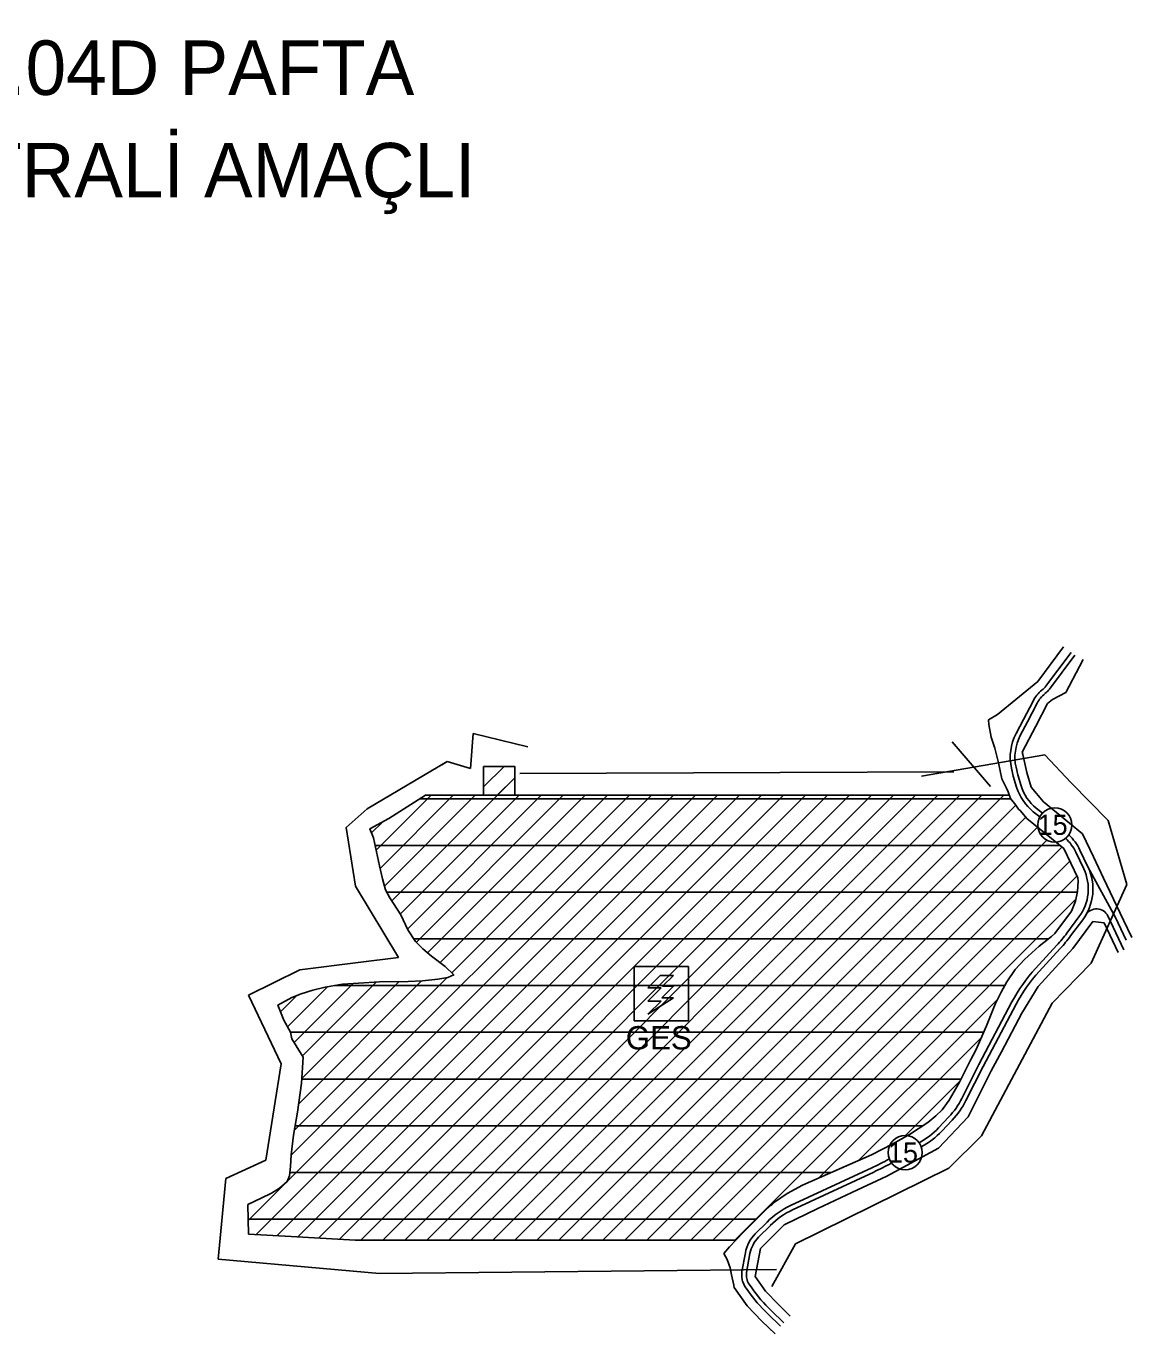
# Model space of a CAD drawing. Extents: x 449035 to 450868, y 4452351 to 4453762.
# Drawn here: x 450158 to 450868, y 4452922 to 4453762 of the extents above; entities that cross this region are included whole.
import ezdxf

# ---------------------------------------------------------------- set-up
doc = ezdxf.new("R2010")
doc.units = 0
for name, color, linetype in [('ADAKENARI', 7, 'Continuous'), ('KALDIRIM', 7, 'Continuous'), ('KD_DAIRE', 7, 'Continuous'), ('KD_YGEN', 7, 'Continuous'), ('LEJAND', 7, 'Continuous'), ('PL_ENERJI_URETIM_ALANI', 7, 'Continuous'), ('SN_ONAY', 7, 'Continuous'), ('TR_ENERJİSANTRALİ', 7, 'Continuous')]:
    doc.layers.add(name, color=color, linetype=linetype)

msp = doc.modelspace()

# ---------------------------------------------------------------- linework, layer by layer
at = {"layer": 'ADAKENARI'}
for p, q in [((450824.18, 4453363.2), (450807.57, 4453340.96)), ((450825.74, 4453333.78), (450834.53, 4453350.62)), ((450834.53, 4453350.62), (450836.81, 4453354.98)), ((450807.57, 4453340.96), (450781.78, 4453319.66)), ((450817.01, 4453329.31), (450825.74, 4453333.78)), ((450806.35, 4453312.31), (450813.88, 4453326.71)), ((450813.88, 4453326.71), (450817.01, 4453329.31)), ((450781.78, 4453319.66), (450776.04, 4453316.41)), ((450776.04, 4453316.41), (450776.14, 4453313.23)), ((450776.14, 4453313.23), (450777.78, 4453305.26)), ((450797.56, 4453295.47), (450806.35, 4453312.31)), ((450777.78, 4453305.26), (450780.06, 4453298.05)), ((450780.06, 4453298.05), (450782.35, 4453288.76)), ((450797.98, 4453294.12), (450797.56, 4453295.47)), ((450800.55, 4453282.48), (450797.98, 4453294.12)), ((450451.63, 4453286.37), (450471.63, 4453286.38)), ((450451.63, 4453267.87), (450451.63, 4453286.37)), ((450471.63, 4453286.38), (450471.63, 4453267.88)), ((450782.35, 4453288.76), (450784.61, 4453278.47)), ((450803.49, 4453273), (450800.55, 4453282.48)), ((450784.61, 4453278.47), (450787.46, 4453272.39)), ((450390.67, 4453252.84), (450414.21, 4453267.86)), ((450390.67, 4453252.84), (450414.21, 4453267.86)), ((450390.67, 4453252.84), (450414.21, 4453267.86)), ((450390.67, 4453252.84), (450414.21, 4453267.86)), ((450414.21, 4453267.86), (450789.35, 4453267.95)), ((450414.21, 4453267.86), (450604.66, 4453267.86)), ((450604.66, 4453267.86), (450760.62, 4453267.94)), ((450787.46, 4453272.39), (450788.71, 4453270)), ((450788.71, 4453270), (450790.03, 4453265.75)), ((450790.03, 4453265.75), (450793.57, 4453261.44)), ((450811.24, 4453263.57), (450803.49, 4453273)), ((450793.57, 4453261.44), (450795.26, 4453258.99)), ((450795.26, 4453258.99), (450796.46, 4453257.93)), ((450796.46, 4453257.93), (450800.61, 4453252.88)), ((450836.35, 4453243.16), (450811.24, 4453263.57)), ((450378.54, 4453246.21), (450390.67, 4453252.84)), ((450800.61, 4453252.88), (450824.27, 4453233.65)), ((450380.9, 4453240.56), (450378.54, 4453246.21)), ((450384.82, 4453222.49), (450380.9, 4453240.56)), ((450843.48, 4453228.19), (450836.35, 4453243.16)), ((450824.27, 4453233.65), (450833.29, 4453214.69)), ((450849.92, 4453214.64), (450843.48, 4453228.19)), ((450386.62, 4453214.14), (450384.82, 4453222.49)), ((450388.63, 4453207.09), (450386.62, 4453214.14)), ((450391.4, 4453201.98), (450388.63, 4453207.09)), ((450833.53, 4453212.67), (450833.25, 4453206.06)), ((450833.29, 4453214.69), (450833.53, 4453212.67)), ((450856.36, 4453201.09), (450849.92, 4453214.64)), ((450398.38, 4453190.97), (450391.4, 4453201.98)), ((450831.92, 4453199.81), (450829.4, 4453193.37)), ((450833.25, 4453206.06), (450831.92, 4453199.81)), ((450862.81, 4453187.55), (450856.36, 4453201.09)), ((450402.95, 4453181.4), (450398.38, 4453190.97)), ((450829.4, 4453193.37), (450818.7, 4453179.06)), ((450407.91, 4453173.99), (450402.95, 4453181.4)), ((450830.26, 4453169.47), (450843.1, 4453186.64)), ((450843.09, 4453186.64), (450850.3, 4453185.92)), ((450850.3, 4453185.92), (450859.36, 4453166.85)), ((450868.07, 4453176.5), (450862.81, 4453187.55)), ((450412.59, 4453169.17), (450407.91, 4453173.99)), ((450816.52, 4453177.06), (450808.48, 4453170.81)), ((450818.66, 4453179.01), (450816.52, 4453177.06)), ((450818.7, 4453179.06), (450818.66, 4453179.01)), ((450418.16, 4453164.49), (450412.59, 4453169.17)), ((450808.48, 4453170.81), (450799.04, 4453162.33)), ((450807.85, 4453145.06), (450830.26, 4453169.47)), ((450426.94, 4453157.87), (450418.16, 4453164.49)), ((450432.47, 4453152.47), (450426.94, 4453157.87)), ((450799.04, 4453162.33), (450793.2, 4453155.91)), ((450371.23, 4453147.14), (450384.82, 4453148.08)), ((450371.23, 4453147.14), (450384.82, 4453148.08)), ((450384.82, 4453148.08), (450403.2, 4453148.22)), ((450384.82, 4453148.08), (450403.2, 4453148.22)), ((450403.2, 4453148.22), (450412.33, 4453148.58)), ((450403.2, 4453148.22), (450412.33, 4453148.58)), ((450412.33, 4453148.58), (450422.19, 4453149.59)), ((450412.33, 4453148.58), (450422.19, 4453149.59)), ((450422.19, 4453149.59), (450428.59, 4453150.74)), ((450422.19, 4453149.59), (450428.59, 4453150.74)), ((450428.59, 4453150.74), (450432.47, 4453152.47)), ((450428.59, 4453150.74), (450432.47, 4453152.47)), ((450787.83, 4453148), (450784.07, 4453141.3)), ((450793.2, 4453155.91), (450787.83, 4453148)), ((450328.4, 4453137.86), (450334.51, 4453140.31)), ((450328.4, 4453137.86), (450334.51, 4453140.31)), ((450334.51, 4453140.31), (450341.92, 4453142.61)), ((450334.51, 4453140.31), (450341.92, 4453142.61)), ((450341.92, 4453142.61), (450349.9, 4453144.48)), ((450341.92, 4453142.61), (450349.9, 4453144.48)), ((450349.9, 4453144.48), (450360.94, 4453146.42)), ((450349.9, 4453144.48), (450360.94, 4453146.42)), ((450360.94, 4453146.42), (450371.23, 4453147.14)), ((450360.94, 4453146.42), (450371.23, 4453147.14)), ((450784.07, 4453141.3), (450780.29, 4453133.73)), ((450797.36, 4453127.77), (450807.85, 4453145.06)), ((450319.53, 4453133.01), (450328.4, 4453137.86)), ((450319.53, 4453133.01), (450328.4, 4453137.86)), ((450323.28, 4453123.26), (450319.53, 4453133.01)), ((450323.28, 4453123.26), (450319.53, 4453133.01)), ((450780.29, 4453133.73), (450774.78, 4453119.79)), ((450327.58, 4453115.55), (450323.28, 4453123.26)), ((450327.58, 4453115.55), (450323.28, 4453123.26)), ((450784.24, 4453102.96), (450797.36, 4453127.77)), ((450328.36, 4453111.35), (450327.58, 4453115.55)), ((450328.36, 4453111.35), (450327.58, 4453115.55)), ((450774.78, 4453119.79), (450767.83, 4453104)), ((450335.77, 4453099.64), (450328.36, 4453111.35)), ((450335.77, 4453099.64), (450328.36, 4453111.35)), ((450334.55, 4453082.96), (450335.77, 4453099.64)), ((450334.55, 4453082.96), (450335.77, 4453099.64)), ((450764.46, 4453097.64), (450757.1, 4453082.99)), ((450767.83, 4453104), (450764.46, 4453097.64)), ((450777.8, 4453090.76), (450784.24, 4453102.96)), ((450763, 4453061.34), (450777.8, 4453090.76)), ((450332.01, 4453064.32), (450334.55, 4453082.96)), ((450332.01, 4453064.32), (450334.55, 4453082.96)), ((450757.1, 4453082.99), (450755.63, 4453080.5)), ((450755.63, 4453080.5), (450750.72, 4453072.02)), ((450329.4, 4453049.39), (450332.01, 4453064.32)), ((450329.4, 4453049.39), (450332.01, 4453064.32)), ((450746.25, 4453065.69), (450742.19, 4453061.96)), ((450750.72, 4453072.02), (450746.25, 4453065.69)), ((450736.96, 4453057.64), (450725.21, 4453049.89)), ((450742.19, 4453061.96), (450736.96, 4453057.64)), ((450743.95, 4453041.17), (450763, 4453061.34)), ((450328.11, 4453036.82), (450329.4, 4453049.39)), ((450328.11, 4453036.82), (450329.4, 4453049.39)), ((450725.21, 4453049.89), (450714.62, 4453043.87)), ((450714.62, 4453043.87), (450700.84, 4453036.86)), ((450710.63, 4453023.07), (450743.95, 4453041.17)), ((450327.67, 4453029.33), (450328.11, 4453036.82)), ((450327.67, 4453029.33), (450328.11, 4453036.82)), ((450700.84, 4453036.86), (450683.69, 4453029.43)), ((450325.37, 4453019.76), (450326.95, 4453023.43)), ((450325.37, 4453019.76), (450326.95, 4453023.43)), ((450326.95, 4453023.43), (450327.67, 4453029.33)), ((450326.95, 4453023.43), (450327.67, 4453029.33)), ((450667.14, 4453022.13), (450656.55, 4453017.25)), ((450683.69, 4453029.43), (450667.14, 4453022.13)), ((450691.77, 4453014.29), (450710.63, 4453023.07)), ((450315.41, 4453012.13), (450320.59, 4453015.52)), ((450315.41, 4453012.13), (450320.59, 4453015.52)), ((450320.59, 4453015.52), (450325.37, 4453019.76)), ((450320.59, 4453015.52), (450325.37, 4453019.76)), ((450656.55, 4453017.25), (450646.67, 4453012.04)), ((450666.34, 4453002.45), (450691.77, 4453014.29)), ((450300.2, 4453004.86), (450308.79, 4453009.04)), ((450300.2, 4453004.86), (450308.79, 4453009.04)), ((450308.79, 4453009.04), (450315.41, 4453012.13)), ((450308.79, 4453009.04), (450315.41, 4453012.13)), ((450638.48, 4453006.34), (450636.69, 4453004.72)), ((450646.67, 4453012.04), (450638.48, 4453006.34)), ((450300.63, 4452985.94), (450300.2, 4453004.86)), ((450300.63, 4452985.94), (450300.2, 4453004.86)), ((450631.5, 4453000.03), (450618.62, 4452987.09)), ((450632.58, 4453001.01), (450631.5, 4453000.03)), ((450635.92, 4453004.35), (450632.58, 4453001.01)), ((450636.69, 4453004.72), (450635.92, 4453004.35)), ((450644.75, 4452991.96), (450666.34, 4453002.45)), ((450629.44, 4452976.65), (450644.75, 4452991.96)), ((450300.63, 4452985.94), (450328, 4452984.35)), ((450328, 4452984.35), (450300.63, 4452985.94)), ((450328, 4452984.35), (450369.18, 4452982.12)), ((450369.18, 4452982.12), (450328, 4452984.35)), ((450369.2, 4452982.12), (450454.69, 4452982.12)), ((450369.2, 4452982.12), (450454.69, 4452982.12)), ((450454.69, 4452982.12), (450613.75, 4452982.12)), ((450454.69, 4452982.12), (450613.75, 4452982.12)), ((450618.62, 4452987.09), (450609.5, 4452977.79)), ((450609.5, 4452977.79), (450605.94, 4452973.38)), ((450605.94, 4452973.38), (450608.03, 4452969.59)), ((450626.18, 4452958.58), (450629.44, 4452976.65)), ((450608.03, 4452969.59), (450610.09, 4452964.14)), ((450610.09, 4452964.14), (450610.88, 4452959.84)), ((450610.88, 4452959.84), (450612.46, 4452953.19)), ((450632.68, 4452949.27), (450626.18, 4452958.58)), ((450612.28, 4452952.87), (450612.46, 4452953.19)), ((450612.28, 4452952.87), (450612.68, 4452951.7)), ((450612.68, 4452951.7), (450621.05, 4452939.73)), ((450640.97, 4452940.63), (450632.68, 4452949.27)), ((450621.05, 4452939.73), (450630.34, 4452930.05)), ((450648.63, 4452933.21), (450640.97, 4452940.63)), ((450630.34, 4452930.05), (450638.83, 4452921.83))]:
    msp.add_line(p, q, dxfattribs=at)
at = {"layer": 'KALDIRIM'}
for p, q in [((450828.98, 4453359.61), (450812.68, 4453337.77)), ((450831.39, 4453357.81), (450815.08, 4453335.98)), ((450810.29, 4453335.43), (450811.06, 4453336.06)), ((450812.2, 4453333.12), (450812.97, 4453333.76)), ((450798.37, 4453316.48), (450804.6, 4453328.39)), ((450801.03, 4453315.09), (450807.26, 4453327)), ((450793.71, 4453307.55), (450798.37, 4453316.48)), ((450796.37, 4453306.16), (450801.03, 4453315.09)), ((450791.84, 4453280.17), (450790.74, 4453285.16)), ((450794.74, 4453280.94), (450793.67, 4453285.8)), ((450794.04, 4453273.09), (450791.84, 4453280.17)), ((450796.9, 4453273.97), (450794.74, 4453280.94)), ((450808.86, 4453253.9), (450804.75, 4453257.25)), ((450810.61, 4453256.35), (450806.64, 4453259.57)), ((450839.88, 4453221.78), (450834.73, 4453232.62)), ((450837.17, 4453220.49), (450832.02, 4453231.33)), ((450857.52, 4453189.35), (450839.88, 4453221.78)), ((450852.66, 4453190.28), (450862.97, 4453168.57)), ((450826.35, 4453179.27), (450834.11, 4453189.65)), ((450828.75, 4453177.47), (450836.51, 4453187.85)), ((450864.46, 4453174.78), (450857.52, 4453189.35)), ((450806.25, 4453156.63), (450819.91, 4453171.5)), ((450808.46, 4453154.6), (450822.12, 4453169.47)), ((450769.84, 4453094.96), (450791.06, 4453135.11)), ((450772.5, 4453093.59), (450793.71, 4453133.7)), ((450758.84, 4453073.1), (450769.84, 4453094.96)), ((450761.52, 4453071.75), (450772.5, 4453093.59)), ((450743.87, 4453054.19), (450750.52, 4453061.24)), ((450746.05, 4453052.13), (450752.7, 4453059.18)), ((450712.04, 4453034.08), (450712.24, 4453034.19)), ((450713.47, 4453031.44), (450713.72, 4453031.58)), ((450648.81, 4453004.22), (450700.99, 4453028.51)), ((450650.08, 4453001.5), (450702.26, 4453025.79)), ((450626.17, 4452986.12), (450633.71, 4452993.65)), ((450628.3, 4452983.99), (450635.83, 4452991.53)), ((450617.62, 4452961.82), (450619.8, 4452973.94)), ((450620.57, 4452961.28), (450622.75, 4452973.4)), ((450621.44, 4452949.65), (450619.75, 4452952.07)), ((450623.9, 4452951.37), (450622.21, 4452953.78)), ((450642.37, 4452926.75), (450634.23, 4452934.63)), ((450644.45, 4452928.9), (450636.31, 4452936.79))]:
    msp.add_line(p, q, dxfattribs=at)
for centre, radius, start, end in [((450824.98, 4453317.73), 23, 129.71534, 152.3941), ((450824.98, 4453317.73), 20, 129.71534, 152.3941), ((450804.67, 4453343.76), 10, 309.71534, 323.24646), ((450804.67, 4453343.76), 13, 309.71534, 323.24646), ((450822.96, 4453292.28), 33, 152.43664, 192.45887), ((450822.96, 4453292.28), 30, 152.43664, 192.45887), ((450825.56, 4453282.86), 30, 197.22103, 230.90214), ((450825.56, 4453282.86), 33, 197.22103, 230.90214), ((450804.93, 4453218.44), 30, 25.4361, 46.61051), ((450804.93, 4453218.44), 33, 25.4361, 46.6385), ((450810.08, 4453207.61), 30, 323.22249, 25.4361), ((450810.08, 4453207.61), 33, 323.22249, 25.4361), ((450845.43, 4453186.84), 8, 25.42651, 149.56601), ((450746.25, 4453239.14), 100, 317.43838, 323.22249), ((450746.25, 4453239.14), 103, 317.43838, 323.22249), ((450882.12, 4453086.96), 103, 137.43838, 152.13345), ((450882.12, 4453086.96), 100, 137.43838, 152.13345), ((450714.17, 4453095.57), 50, 316.63566, 333.29481), ((450714.17, 4453095.57), 53, 316.63566, 333.29481), ((450707.52, 4453088.52), 50, 298.51149, 316.63566), ((450707.52, 4453088.52), 53, 298.51149, 316.63566), ((450616.57, 4453209.82), 200, 294.9671, 298.51149), ((450616.57, 4453209.82), 203, 294.9671, 298.51149), ((450671.18, 4452956.17), 53, 114.9671, 134.99991), ((450671.18, 4452956.17), 50, 114.9671, 134.99991), ((450642.44, 4452969.85), 23, 134.99991, 169.77321), ((450642.44, 4452969.85), 20, 134.99991, 169.77321), ((450630.41, 4452959.51), 13, 169.77321, 214.92166), ((450630.41, 4452959.51), 10, 169.77321, 214.92166), ((450705.89, 4453008.61), 103, 214.92166, 225.91171), ((450705.89, 4453008.61), 100, 214.92166, 225.91171)]:
    msp.add_arc(centre, radius, start, end, dxfattribs=at)
at = {"layer": 'KD_DAIRE'}
for centre in [(450818.6, 4453248.78), (450722.46, 4453038.25)]:
    msp.add_circle(centre, 11, dxfattribs=at)
at = {"layer": 'LEJAND'}
for p, q in [((450548.35, 4453157.92), (450583.35, 4453157.92)), ((450548.35, 4453157.92), (450548.35, 4453122.92)), ((450583.35, 4453157.92), (450583.35, 4453122.92)), ((450565.14, 4453152.13), (450557.14, 4453144.13)), ((450573.63, 4453152.13), (450565.14, 4453152.13)), ((450566.63, 4453145.13), (450573.63, 4453152.13)), ((450557.14, 4453144.13), (450565.63, 4453144.13)), ((450565.63, 4453144.13), (450557.14, 4453135.65)), ((450566.14, 4453137.65), (450573.63, 4453145.13)), ((450573.63, 4453145.13), (450566.63, 4453145.13)), ((450557.14, 4453127.16), (450573.63, 4453137.65)), ((450557.14, 4453135.65), (450565.63, 4453135.65)), ((450565.63, 4453135.65), (450557.14, 4453127.16)), ((450573.63, 4453137.65), (450566.14, 4453137.65)), ((450548.35, 4453122.92), (450583.35, 4453122.92))]:
    msp.add_line(p, q, dxfattribs=at)
at = {"layer": 'PL_ENERJI_URETIM_ALANI'}
for points in [[(450451.63, 4453286.37), (450471.63, 4453286.38), (450471.63, 4453267.88), (450451.63, 4453267.87)], [(450414.21, 4453267.86), (450760.62, 4453267.94), (450789.35, 4453267.95), (450788.71, 4453270), (450788.71, 4453270), (450787.46, 4453272.39), (450788.71, 4453270), (450790.03, 4453265.75), (450793.57, 4453261.44), (450795.26, 4453258.99), (450796.46, 4453257.93), (450800.61, 4453252.88), (450824.27, 4453233.65), (450833.29, 4453214.69), (450833.53, 4453212.67), (450833.25, 4453206.06), (450831.92, 4453199.81), (450829.4, 4453193.37), (450818.7, 4453179.06), (450816.52, 4453177.06), (450808.48, 4453170.81), (450799.04, 4453162.33), (450793.2, 4453155.91), (450787.83, 4453148), (450784.07, 4453141.3), (450780.29, 4453133.73), (450774.78, 4453119.79), (450767.83, 4453104), (450764.46, 4453097.64), (450757.1, 4453082.99), (450755.63, 4453080.5), (450750.72, 4453072.02), (450746.25, 4453065.69), (450742.19, 4453061.96), (450736.96, 4453057.64), (450725.21, 4453049.89), (450714.62, 4453043.87), (450700.84, 4453036.86), (450667.14, 4453022.13), (450656.55, 4453017.25), (450646.67, 4453012.04), (450638.48, 4453006.34), (450636.69, 4453004.72), (450635.92, 4453004.35), (450632.58, 4453001.01), (450618.62, 4452987.09), (450613.75, 4452982.12), (450454.69, 4452982.12), (450369.18, 4452982.12), (450328, 4452984.35), (450300.63, 4452985.94), (450300.2, 4453004.86), (450308.79, 4453009.04), (450315.41, 4453012.13), (450320.59, 4453015.52), (450325.37, 4453019.76), (450326.95, 4453023.43), (450327.67, 4453029.33), (450328.11, 4453036.82), (450329.4, 4453049.39), (450332.01, 4453064.32), (450334.55, 4453082.96), (450335.77, 4453099.64), (450328.36, 4453111.35), (450327.58, 4453115.55), (450323.28, 4453123.26), (450319.53, 4453133.01), (450328.4, 4453137.86), (450334.51, 4453140.31), (450341.92, 4453142.61), (450349.9, 4453144.48), (450360.94, 4453146.42), (450371.23, 4453147.14), (450384.82, 4453148.08), (450403.2, 4453148.22), (450412.33, 4453148.58), (450422.19, 4453149.59), (450428.59, 4453150.74), (450432.47, 4453152.47), (450426.94, 4453157.87), (450418.16, 4453164.49), (450412.59, 4453169.17), (450407.91, 4453173.99), (450402.95, 4453181.4), (450398.38, 4453190.97), (450391.4, 4453201.98), (450388.63, 4453207.09), (450386.62, 4453214.14), (450384.82, 4453222.49), (450380.9, 4453240.56), (450378.54, 4453246.21), (450390.67, 4453252.84)]]:
    msp.add_lwpolyline(points, close=True, dxfattribs=at)
at = {"layer": 'SN_ONAY'}
for p, q in [((450443.15, 4453285.03), (450444.94, 4453307.44)), ((450444.94, 4453307.44), (450480.14, 4453298.93)), ((450777.35, 4453273.5), (450752.54, 4453302.26)), ((450732.93, 4453280.09), (450812.08, 4453293.91)), ((450812.08, 4453293.91), (450829.07, 4453275.9)), ((450376.73, 4453259.05), (450428.18, 4453289.47)), ((450424.71, 4453287.43), (450428.18, 4453289.47)), ((450428.18, 4453289.47), (450443.15, 4453285.03)), ((450474.99, 4453281.8), (450753.64, 4453282.81)), ((450829.07, 4453275.9), (450852.86, 4453251.71)), ((450363.33, 4453247.03), (450376.73, 4453259.05)), ((450852.86, 4453251.71), (450864.78, 4453210.43)), ((450369.29, 4453209.42), (450363.33, 4453247.03)), ((450396.95, 4453163.62), (450369.29, 4453209.42)), ((450864.78, 4453210.43), (450841.86, 4453159.97)), ((450333.58, 4453155.76), (450371.03, 4453160.47)), ((450371.03, 4453160.47), (450396.95, 4453163.62)), ((450841.86, 4453159.97), (450816.89, 4453134.32)), ((450300.64, 4453139.44), (450333.58, 4453155.76)), ((450321.63, 4453095.37), (450300.64, 4453139.44)), ((450816.89, 4453134.32), (450771.52, 4453049)), ((450311.66, 4453033.39), (450321.63, 4453095.37)), ((450771.52, 4453049), (450750.44, 4453028.36)), ((450286.08, 4453021.68), (450311.66, 4453033.39)), ((450750.44, 4453028.36), (450651.92, 4452979.74)), ((450281.21, 4452969.86), (450286.08, 4453021.68)), ((450651.92, 4452979.74), (450636.88, 4452952.28)), ((450384.84, 4452960.65), (450281.21, 4452969.86)), ((450384.84, 4452960.65), (450639.7, 4452963.22))]:
    msp.add_line(p, q, dxfattribs=at)
at = {"layer": 'TR_ENERJİSANTRALİ'}
for p, q in [((450451.63, 4453273.22), (450464.78, 4453286.37)), ((450392.62, 4453200.07), (450471.63, 4453279.08)), ((450471.63, 4453279.08), (450460.41, 4453267.86)), ((450300.43, 4452994.74), (450573.55, 4453267.86)), ((450305.49, 4452985.66), (450587.69, 4453267.86)), ((450318.85, 4452984.88), (450601.84, 4453267.86)), ((450328.09, 4453036.54), (450559.41, 4453267.86)), ((450332.24, 4452984.12), (450615.98, 4453267.87)), ((450345.65, 4452983.4), (450630.13, 4453267.88)), ((450359.07, 4452982.67), (450644.28, 4453267.88)), ((450372.66, 4452982.12), (450658.43, 4453267.89)), ((450382.65, 4453232.52), (450417.99, 4453267.86)), ((450385.17, 4453220.9), (450432.13, 4453267.86)), ((450386.81, 4452982.12), (450672.58, 4453267.9)), ((450387.94, 4453209.53), (450446.28, 4453267.87)), ((450398.1, 4453191.41), (450474.56, 4453267.86)), ((450400.95, 4452982.12), (450686.73, 4453267.91)), ((450402.72, 4453181.88), (450488.7, 4453267.86)), ((450408.43, 4453173.45), (450502.84, 4453267.86)), ((450410.56, 4453265.54), (450790.2, 4453265.54)), ((450415.09, 4452982.12), (450700.88, 4453267.91)), ((450415.68, 4453166.57), (450516.98, 4453267.86)), ((450423.63, 4453160.36), (450531.12, 4453267.86)), ((450429.23, 4452982.12), (450715.03, 4453267.92)), ((450431.16, 4453153.75), (450545.27, 4453267.86)), ((450443.38, 4452982.12), (450729.18, 4453267.93)), ((450457.52, 4452982.12), (450743.33, 4453267.93)), ((450471.66, 4452982.12), (450757.48, 4453267.94)), ((450485.8, 4452982.12), (450771.62, 4453267.95)), ((450499.94, 4452982.12), (450785.77, 4453267.95)), ((450514.09, 4452982.12), (450793.49, 4453261.53)), ((450379.62, 4453243.63), (450386.59, 4453250.61)), ((450528.23, 4452982.12), (450799.87, 4453253.77)), ((450542.37, 4452982.12), (450807.51, 4453247.27)), ((450381.99, 4453235.54), (450821.95, 4453235.54)), ((450556.51, 4452982.12), (450813.45, 4453239.06)), ((450570.65, 4452982.12), (450823.12, 4453234.59)), ((450584.8, 4452982.12), (450828.15, 4453225.48)), ((450598.94, 4452982.12), (450832.71, 4453215.9)), ((450389.48, 4453205.54), (450833.14, 4453205.54)), ((450613.08, 4452982.12), (450832.23, 4453201.27)), ((450406.87, 4453175.54), (450814.57, 4453175.54)), ((450329.96, 4453052.55), (450428.05, 4453150.64)), ((450332.71, 4453069.45), (450411.82, 4453148.56)), ((450334.74, 4453085.62), (450397.3, 4453148.18)), ((450335.32, 4453100.35), (450382.93, 4453147.95)), ((450325.67, 4453118.97), (450351.44, 4453144.75)), ((450329.84, 4453109.01), (450367.73, 4453146.9)), ((450355.91, 4453145.54), (450786.45, 4453145.54)), ((450321.21, 4453128.66), (450331.75, 4453139.2)), ((450667.3, 4453022.2), (450781.75, 4453136.65)), ((450327.58, 4453115.54), (450772.91, 4453115.54)), ((450692.48, 4453033.23), (450771.44, 4453112.2)), ((450334.74, 4453085.54), (450758.38, 4453085.54)), ((450722.63, 4453049.25), (450757.83, 4453084.45)), ((450330.48, 4453055.54), (450733.78, 4453055.54)), ((450327.21, 4453025.54), (450674.87, 4453025.54)), ((450300.41, 4452995.54), (450627.03, 4452995.54))]:
    msp.add_line(p, q, dxfattribs=at)

# ---------------------------------------------------------------- texts
at = {"layer": 'KD_YGEN'}
for p in [(450807.5, 4453242.39), (450711.36, 4453031.86)]:
    msp.add_text('15', height=13, dxfattribs=at).set_placement(p)
at = {"layer": 'LEJAND'}
for s, height, p in [('BURSA İLİ KESTEL İLÇESİ SOĞUKSU KÖYÜ H22C.04D PAFTA ', 35, (449038.98, 4453717.77)), ('9, 1114, 1116 PARSELLER GÜNEŞ ENERJİSİ SANTRALİ AMAÇLI', 35, (449038.98, 4453651.94)), ('GES', 15, (450542.95, 4453104.53))]:
    msp.add_text(s, height=height, dxfattribs=at).set_placement(p)

doc.saveas('drawing.dxf')
